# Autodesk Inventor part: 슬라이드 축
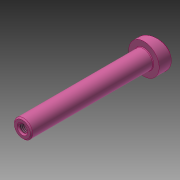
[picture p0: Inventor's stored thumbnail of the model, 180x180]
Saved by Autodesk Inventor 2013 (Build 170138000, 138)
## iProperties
Created: 2015-11
Part Number: 슬라이드 축
Document SubType Name: 모델링
Designer: mdu
Mass: 169.296 g
Surface Area: 66.7318 cm^2
Volume: 20.9525 cm^3
Density: 8.08 g/cm^3
Material: 스테인리스강
변환 표준: STEP AP214IS
파일 이름: C:\Users\SeoGD\Desktop\?쒗뿕\異?stp
전처리기: Build: 253, Release: 2010 SP1 - Date: Wed 07/29/2009
전송 단위: 밀리미터
불확실성: 0.01
Author: mdu
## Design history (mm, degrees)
sketch "스케치1"
  geometry: L1 (0, 100)-(7.5, 100); L2 (7.5, 100)-(7.5, 0); L3 (7.5, 0)-(12.5, 0); L4 (12.5, 0)-(12.5, -17); L5 (12.5, -17)-(0, -17); L6 (0, -17)-(0, 100); 1 further point
  constraints: 12 end point, 2 parallel, 2 point on line, 1 perpendicular, 1 vertical
  dimensions: "d0" = 100 distance from line of L1 point (0, 0); "d1" = 15 diameter of L2 L6; "d2" = 25 diameter of L4 L6; "d3" = 17 distance of L3.end L4.end
revolve "회전1" sketch "스케치1" stored, may be unused: angle "d4" = 90 deg
sketch "스케치2"
  geometry: L1 (12.5, 0)-(12.5, -17) reference; L2 (-12.5, -17)-(12.5, -17) reference; L3 (-12.5, 0)-(-12.5, -17) reference; L4 (12.5, -5)-(-12.5, -11.699); L5 (-12.5, 0)-(12.5, 0) reference; 1 further point
  constraints: 2 end point, 2 point on line
  dimensions: "d5" = 75 deg angle of L1 L4; "d6" = 5 distance from line of L4.start L5
extrude "돌출1" cut sketch "스케치2" stored distance "d7" = 10; taper "d8" = 0 deg
chamfer "모따기1" distance "d9" = 1; stored, may be unused: second distance "d10" = 2, angle "d11" = 45 deg
fillet "모깎기1" dims "d12" = 0.5
hole "구멍1" diameter "d15" = 6.647; stored, may be unused: countersink angle "d19" = 90 deg, drill point angle "d21" = 118 deg; dims "d13" = 10, "d14" = 10, "d16" = 17, "d17" = 4, "d18" = 2, "d20" = 20
chamfer "모따기2" distance "d22" = 1; stored, may be unused: second distance "d23" = 2, angle "d24" = 45 deg
node "솔리드1"
node "솔리드 본체"
node "곡면 본체"
node "솔리드2"
